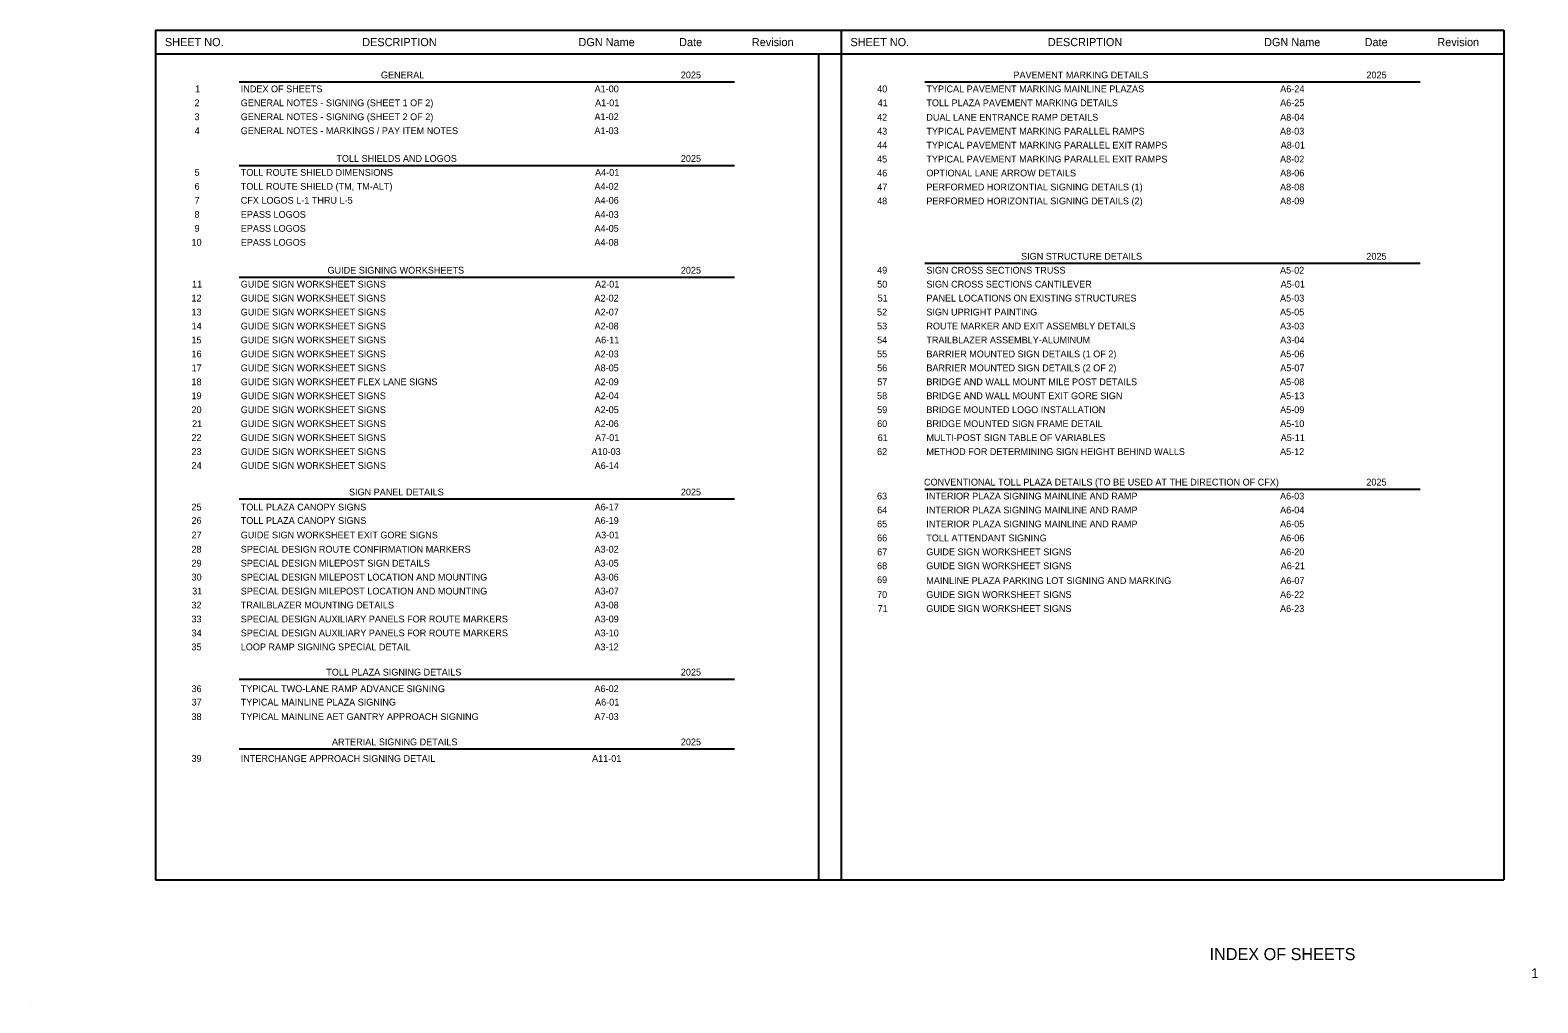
# Model space of a CAD drawing. Extents: x 2479979.8 to 2479999.3, y 3680687.9 to 3680700.4.
import ezdxf

# ---------------------------------------------------------------- set-up
doc = ezdxf.new("R2010")
doc.units = 0
for name, color, linetype in [('AdhocPoint_dp', 7, 'Continuous'), ('SumBoxLines_dp', 7, 'Continuous'), ('TextLabel', 7, 'Continuous'), ('TextMisc', 7, 'Continuous'), ('TextShtNo', 7, 'Continuous')]:
    doc.layers.add(name, color=color, linetype=linetype)

msp = doc.modelspace()

# ---------------------------------------------------------------- linework, layer by layer
at = {"layer": 'AdhocPoint_dp'}
msp.add_line((2479979.842, 3680687.871), (2479979.842, 3680687.871), dxfattribs=at)
at = {"layer": 'SumBoxLines_dp'}
for p, q in [((2479981.458, 3680700.422), (2479998.85, 3680700.422)), ((2479981.458, 3680700.422), (2479981.458, 3680689.458)), ((2479990.3, 3680700.422), (2479990.3, 3680690.034)), ((2479998.85, 3680700.422), (2479998.85, 3680689.458)), ((2479981.458, 3680700.114), (2479998.85, 3680700.114)), ((2479981.458, 3680700.114), (2479998.85, 3680700.114)), ((2479990.008, 3680700.114), (2479990.008, 3680691.294)), ((2479990.008, 3680700.025), (2479990.008, 3680689.458)), ((2479990.3, 3680700.025), (2479990.3, 3680689.458)), ((2479982.538, 3680699.754), (2479988.928, 3680699.754)), ((2479982.538, 3680699.754), (2479988.928, 3680699.754)), ((2479991.381, 3680699.754), (2479997.771, 3680699.754)), ((2479991.381, 3680699.754), (2479997.771, 3680699.754)), ((2479982.538, 3680698.675), (2479988.928, 3680698.675)), ((2479982.538, 3680698.675), (2479988.928, 3680698.675)), ((2479991.381, 3680697.414), (2479997.771, 3680697.414)), ((2479991.381, 3680697.414), (2479997.771, 3680697.414)), ((2479982.538, 3680697.234), (2479988.928, 3680697.234)), ((2479982.538, 3680697.234), (2479988.928, 3680697.234)), ((2479991.38, 3680694.5), (2479997.77, 3680694.5)), ((2479991.38, 3680694.5), (2479997.77, 3680694.5)), ((2479982.538, 3680694.372), (2479988.928, 3680694.372)), ((2479982.538, 3680692.047), (2479988.928, 3680692.047)), ((2479982.538, 3680692.047), (2479988.928, 3680692.047)), ((2479982.538, 3680691.147), (2479988.928, 3680691.147)), ((2479982.538, 3680691.147), (2479988.928, 3680691.147)), ((2479981.458, 3680689.458), (2479998.85, 3680689.458))]:
    msp.add_line(p, q, dxfattribs=at)

# ---------------------------------------------------------------- texts
at = {"layer": 'TextLabel'}
for s, height, p in [('SHEET NO.', 0.105, (2479981.58, 3680700.215)), ('DESCRIPTION', 0.105, (2479984.125, 3680700.215)), ('DGN Name', 0.105, (2479986.914, 3680700.215)), ('Date', 0.105, (2479988.212, 3680700.215)), ('Revision', 0.105, (2479989.15, 3680700.215)), ('SHEET NO.', 0.105, (2479990.422, 3680700.215)), ('DESCRIPTION', 0.105, (2479992.968, 3680700.215)), ('DGN Name', 0.105, (2479995.757, 3680700.215)), ('Date', 0.105, (2479997.054, 3680700.215)), ('Revision', 0.105, (2479997.992, 3680700.215)), ('GENERAL', 0.0875, (2479984.366, 3680699.8)), ('2025', 0.0875, (2479988.234, 3680699.8)), ('PAVEMENT MARKING DETAILS', 0.0875, (2479992.524, 3680699.8)), ('2025', 0.0875, (2479997.077, 3680699.8)), ('2', 0.0875, (2479981.961, 3680699.44)), ('1', 0.0875, (2479981.969, 3680699.62)), ('GENERAL NOTES - SIGNING (SHEET 1 OF 2)', 0.0875, (2479982.558, 3680699.44)), ('INDEX OF SHEETS', 0.0875, (2479982.558, 3680699.62)), ('A1-00', 0.0875, (2479987.121, 3680699.62)), ('A1-01', 0.0875, (2479987.128, 3680699.44)), ('40', 0.0875, (2479990.766, 3680699.62)), ('41', 0.0875, (2479990.773, 3680699.44)), ('TYPICAL PAVEMENT MARKING MAINLINE PLAZAS', 0.0875, (2479991.401, 3680699.62)), ('TOLL PLAZA PAVEMENT MARKING DETAILS', 0.0875, (2479991.401, 3680699.44)), ('A6-25', 0.0875, (2479995.964, 3680699.44)), ('A6-24', 0.0875, (2479995.965, 3680699.62)), ('3', 0.0875, (2479981.961, 3680699.26)), ('GENERAL NOTES - SIGNING (SHEET 2 OF 2)', 0.0875, (2479982.558, 3680699.26)), ('A1-02', 0.0875, (2479987.12, 3680699.26)), ('42', 0.0875, (2479990.765, 3680699.254)), ('DUAL LANE ENTRANCE RAMP DETAILS', 0.0875, (2479991.401, 3680699.254)), ('A8-04', 0.0875, (2479995.965, 3680699.254)), ('4', 0.0875, (2479981.963, 3680699.08)), ('GENERAL NOTES - MARKINGS / PAY ITEM NOTES', 0.0875, (2479982.558, 3680699.08)), ('A1-03', 0.0875, (2479987.12, 3680699.08)), ('43', 0.0875, (2479990.765, 3680699.074)), ('TYPICAL PAVEMENT MARKING PARALLEL RAMPS', 0.0875, (2479991.401, 3680699.074)), ('A8-03', 0.0875, (2479995.963, 3680699.074)), ('44', 0.0875, (2479990.766, 3680698.894)), ('TYPICAL PAVEMENT MARKING PARALLEL EXIT RAMPS', 0.0875, (2479991.401, 3680698.894)), ('A8-01', 0.0875, (2479995.971, 3680698.894)), ('TOLL SHIELDS AND LOGOS', 0.0875, (2479983.791, 3680698.722)), ('2025', 0.0875, (2479988.234, 3680698.722)), ('45', 0.0875, (2479990.765, 3680698.714)), ('TYPICAL PAVEMENT MARKING PARALLEL EXIT RAMPS', 0.0875, (2479991.401, 3680698.714)), ('A8-02', 0.0875, (2479995.963, 3680698.714)), ('5', 0.0875, (2479981.962, 3680698.542)), ('TOLL ROUTE SHIELD DIMENSIONS', 0.0875, (2479982.558, 3680698.542)), ('A4-01', 0.0875, (2479987.128, 3680698.542)), ('46', 0.0875, (2479990.766, 3680698.534)), ('OPTIONAL LANE ARROW DETAILS', 0.0875, (2479991.401, 3680698.534)), ('A8-06', 0.0875, (2479995.964, 3680698.534)), ('6', 0.0875, (2479981.962, 3680698.362)), ('TOLL ROUTE SHIELD (TM, TM-ALT)', 0.0875, (2479982.558, 3680698.362)), ('A4-02', 0.0875, (2479987.12, 3680698.362)), ('47', 0.0875, (2479990.767, 3680698.354)), ('PERFORMED HORIZONTIAL SIGNING DETAILS (1)', 0.0875, (2479991.401, 3680698.354)), ('A8-08', 0.0875, (2479995.963, 3680698.354)), ('7', 0.0875, (2479981.963, 3680698.182)), ('CFX LOGOS L-1 THRU L-5', 0.0875, (2479982.558, 3680698.182)), ('A4-06', 0.0875, (2479987.121, 3680698.182)), ('48', 0.0875, (2479990.765, 3680698.174)), ('PERFORMED HORIZONTIAL SIGNING DETAILS (2)', 0.0875, (2479991.401, 3680698.174)), ('A8-09', 0.0875, (2479995.964, 3680698.174)), ('8', 0.0875, (2479981.961, 3680698)), ('EPASS LOGOS', 0.0875, (2479982.558, 3680698)), ('A4-03', 0.0875, (2479987.12, 3680698)), ('9', 0.0875, (2479981.962, 3680697.82)), ('EPASS LOGOS', 0.0875, (2479982.558, 3680697.82)), ('A4-05', 0.0875, (2479987.121, 3680697.82)), ('10', 0.0875, (2479981.923, 3680697.64)), ('EPASS LOGOS', 0.0875, (2479982.558, 3680697.64)), ('A4-08', 0.0875, (2479987.12, 3680697.64)), ('SIGN STRUCTURE DETAILS', 0.0875, (2479992.623, 3680697.46)), ('2025', 0.0875, (2479997.076, 3680697.46)), ('11', 0.0875, (2479981.93, 3680697.1)), ('GUIDE SIGN WORKSHEET SIGNS', 0.0875, (2479982.558, 3680697.1)), ('GUIDE SIGNING WORKSHEETS', 0.0875, (2479983.677, 3680697.28)), ('A2-01', 0.0875, (2479987.128, 3680697.1)), ('2025', 0.0875, (2479988.234, 3680697.28)), ('49', 0.0875, (2479990.766, 3680697.28)), ('50', 0.0875, (2479990.766, 3680697.1)), ('SIGN CROSS SECTIONS TRUSS', 0.0875, (2479991.401, 3680697.28)), ('SIGN CROSS SECTIONS CANTILEVER', 0.0875, (2479991.401, 3680697.1)), ('A5-02', 0.0875, (2479995.963, 3680697.28)), ('A5-01', 0.0875, (2479995.971, 3680697.1)), ('12', 0.0875, (2479981.922, 3680696.92)), ('GUIDE SIGN WORKSHEET SIGNS', 0.0875, (2479982.558, 3680696.92)), ('A2-02', 0.0875, (2479987.12, 3680696.92)), ('51', 0.0875, (2479990.773, 3680696.92)), ('PANEL LOCATIONS ON EXISTING STRUCTURES', 0.0875, (2479991.401, 3680696.92)), ('A5-03', 0.0875, (2479995.963, 3680696.92)), ('13', 0.0875, (2479981.922, 3680696.74)), ('GUIDE SIGN WORKSHEET SIGNS', 0.0875, (2479982.558, 3680696.74)), ('A2-07', 0.0875, (2479987.122, 3680696.74)), ('52', 0.0875, (2479990.765, 3680696.74)), ('SIGN UPRIGHT PAINTING', 0.0875, (2479991.401, 3680696.74)), ('A5-05', 0.0875, (2479995.963, 3680696.74)), ('14', 0.0875, (2479981.924, 3680696.56)), ('GUIDE SIGN WORKSHEET SIGNS', 0.0875, (2479982.558, 3680696.56)), ('A2-08', 0.0875, (2479987.12, 3680696.56)), ('53', 0.0875, (2479990.765, 3680696.56)), ('ROUTE MARKER AND EXIT ASSEMBLY DETAILS', 0.0875, (2479991.401, 3680696.56)), ('A3-03', 0.0875, (2479995.963, 3680696.56)), ('15', 0.0875, (2479981.922, 3680696.38)), ('GUIDE SIGN WORKSHEET SIGNS', 0.0875, (2479982.558, 3680696.38)), ('A6-11', 0.0875, (2479987.128, 3680696.38)), ('54', 0.0875, (2479990.766, 3680696.38)), ('TRAILBLAZER ASSEMBLY-ALUMINUM', 0.0875, (2479991.401, 3680696.38)), ('A3-04', 0.0875, (2479995.965, 3680696.38)), ('16', 0.0875, (2479981.923, 3680696.2)), ('GUIDE SIGN WORKSHEET SIGNS', 0.0875, (2479982.558, 3680696.2)), ('A2-03', 0.0875, (2479987.12, 3680696.2)), ('55', 0.0875, (2479990.765, 3680696.2)), ('BARRIER MOUNTED SIGN DETAILS (1 OF 2)', 0.0875, (2479991.401, 3680696.2)), ('A5-06', 0.0875, (2479995.964, 3680696.2)), ('17', 0.0875, (2479981.924, 3680696.02)), ('GUIDE SIGN WORKSHEET SIGNS', 0.0875, (2479982.558, 3680696.02)), ('A8-05', 0.0875, (2479987.121, 3680696.02)), ('56', 0.0875, (2479990.766, 3680696.02)), ('BARRIER MOUNTED SIGN DETAILS (2 OF 2)', 0.0875, (2479991.401, 3680696.02)), ('A5-07', 0.0875, (2479995.965, 3680696.02)), ('18', 0.0875, (2479981.922, 3680695.84)), ('GUIDE SIGN WORKSHEET FLEX LANE SIGNS', 0.0875, (2479982.558, 3680695.84)), ('A2-09', 0.0875, (2479987.121, 3680695.84)), ('57', 0.0875, (2479990.767, 3680695.84)), ('BRIDGE AND WALL MOUNT MILE POST DETAILS', 0.0875, (2479991.401, 3680695.84)), ('A5-08', 0.0875, (2479995.963, 3680695.84)), ('19', 0.0875, (2479981.923, 3680695.66)), ('GUIDE SIGN WORKSHEET SIGNS', 0.0875, (2479982.558, 3680695.66)), ('A2-04', 0.0875, (2479987.122, 3680695.66)), ('58', 0.0875, (2479990.765, 3680695.66)), ('BRIDGE AND WALL MOUNT EXIT GORE SIGN', 0.0875, (2479991.401, 3680695.66)), ('A5-13', 0.0875, (2479995.963, 3680695.66)), ('20', 0.0875, (2479981.923, 3680695.48)), ('GUIDE SIGN WORKSHEET SIGNS', 0.0875, (2479982.558, 3680695.48)), ('A2-05', 0.0875, (2479987.121, 3680695.48)), ('59', 0.0875, (2479990.766, 3680695.48)), ('BRIDGE MOUNTED LOGO INSTALLATION', 0.0875, (2479991.401, 3680695.48)), ('A5-09', 0.0875, (2479995.964, 3680695.48)), ('21', 0.0875, (2479981.93, 3680695.3)), ('GUIDE SIGN WORKSHEET SIGNS', 0.0875, (2479982.558, 3680695.3)), ('A2-06', 0.0875, (2479987.121, 3680695.3)), ('60', 0.0875, (2479990.766, 3680695.3)), ('BRIDGE MOUNTED SIGN FRAME DETAIL', 0.0875, (2479991.401, 3680695.3)), ('A5-10', 0.0875, (2479995.964, 3680695.3)), ('22', 0.0875, (2479981.922, 3680695.12)), ('GUIDE SIGN WORKSHEET SIGNS', 0.0875, (2479982.558, 3680695.12)), ('A7-01', 0.0875, (2479987.128, 3680695.12)), ('61', 0.0875, (2479990.773, 3680695.12)), ('MULTI-POST SIGN TABLE OF VARIABLES', 0.0875, (2479991.401, 3680695.12)), ('A5-11', 0.0875, (2479995.971, 3680695.12)), ('23', 0.0875, (2479981.922, 3680694.94)), ('GUIDE SIGN WORKSHEET SIGNS', 0.0875, (2479982.558, 3680694.94)), ('A10-03', 0.0875, (2479987.081, 3680694.94)), ('62', 0.0875, (2479990.765, 3680694.94)), ('METHOD FOR DETERMINING SIGN HEIGHT BEHIND WALLS', 0.0875, (2479991.401, 3680694.94)), ('A5-12', 0.0875, (2479995.963, 3680694.94)), ('24', 0.0875, (2479981.924, 3680694.76)), ('GUIDE SIGN WORKSHEET SIGNS', 0.0875, (2479982.558, 3680694.76)), ('A6-14', 0.0875, (2479987.122, 3680694.76)), ('SIGN PANEL DETAILS', 0.0875, (2479983.954, 3680694.418)), ('2025', 0.0875, (2479988.234, 3680694.418)), ('CONVENTIONAL TOLL PLAZA DETAILS (TO BE USED AT THE DIRECTION OF CFX)', 0.0875, (2479991.371, 3680694.546)), ('2025', 0.0875, (2479997.076, 3680694.546)), ('25', 0.0875, (2479981.922, 3680694.224)), ('TOLL PLAZA CANOPY SIGNS', 0.0875, (2479982.558, 3680694.224)), ('A6-17', 0.0875, (2479987.122, 3680694.224)), ('63', 0.0875, (2479990.764, 3680694.366)), ('64', 0.0875, (2479990.766, 3680694.186)), ('INTERIOR PLAZA SIGNING MAINLINE AND RAMP', 0.0875, (2479991.4, 3680694.366)), ('INTERIOR PLAZA SIGNING MAINLINE AND RAMP', 0.0875, (2479991.4, 3680694.186)), ('A6-03', 0.0875, (2479995.963, 3680694.366)), ('A6-04', 0.0875, (2479995.964, 3680694.186)), ('26', 0.0875, (2479981.923, 3680694.051)), ('TOLL PLAZA CANOPY SIGNS', 0.0875, (2479982.558, 3680694.051)), ('A6-19', 0.0875, (2479987.121, 3680694.051)), ('65', 0.0875, (2479990.765, 3680694.006)), ('INTERIOR PLAZA SIGNING MAINLINE AND RAMP', 0.0875, (2479991.4, 3680694.006)), ('A6-05', 0.0875, (2479995.963, 3680694.006)), ('27', 0.0875, (2479981.924, 3680693.864)), ('GUIDE SIGN WORKSHEET EXIT GORE SIGNS', 0.0875, (2479982.558, 3680693.864)), ('A3-01', 0.0875, (2479987.128, 3680693.864)), ('66', 0.0875, (2479990.765, 3680693.826)), ('TOLL ATTENDANT SIGNING', 0.0875, (2479991.4, 3680693.826)), ('A6-06', 0.0875, (2479995.964, 3680693.826)), ('28', 0.0875, (2479981.922, 3680693.68)), ('SPECIAL DESIGN ROUTE CONFIRMATION MARKERS', 0.0875, (2479982.558, 3680693.68)), ('A3-02', 0.0875, (2479987.12, 3680693.68)), ('67', 0.0875, (2479990.766, 3680693.646)), ('GUIDE SIGN WORKSHEET SIGNS ', 0.0875, (2479991.4, 3680693.646)), ('A6-20', 0.0875, (2479995.964, 3680693.646)), ('29', 0.0875, (2479981.923, 3680693.5)), ('SPECIAL DESIGN MILEPOST SIGN DETAILS', 0.0875, (2479982.558, 3680693.5)), ('A3-05', 0.0875, (2479987.121, 3680693.5)), ('68', 0.0875, (2479990.765, 3680693.466)), ('GUIDE SIGN WORKSHEET SIGNS ', 0.0875, (2479991.4, 3680693.466)), ('A6-21', 0.0875, (2479995.971, 3680693.466)), ('30', 0.0875, (2479981.923, 3680693.32)), ('SPECIAL DESIGN MILEPOST LOCATION AND MOUNTING', 0.0875, (2479982.558, 3680693.32)), ('A3-06', 0.0875, (2479987.121, 3680693.32)), ('69', 0.0875, (2479990.765, 3680693.286)), ('MAINLINE PLAZA PARKING LOT SIGNING AND MARKING', 0.0875, (2479991.4, 3680693.275)), ('A6-07', 0.0875, (2479995.965, 3680693.275)), ('31', 0.0875, (2479981.93, 3680693.14)), ('SPECIAL DESIGN MILEPOST LOCATION AND MOUNTING', 0.0875, (2479982.558, 3680693.14)), ('A3-07', 0.0875, (2479987.122, 3680693.14)), ('70', 0.0875, (2479990.765, 3680693.095)), ('GUIDE SIGN WORKSHEET SIGNS', 0.0875, (2479991.4, 3680693.095)), ('A6-22', 0.0875, (2479995.963, 3680693.095)), ('32', 0.0875, (2479981.922, 3680692.96)), ('TRAILBLAZER MOUNTING DETAILS', 0.0875, (2479982.558, 3680692.96)), ('A3-08', 0.0875, (2479987.12, 3680692.96)), ('71', 0.0875, (2479990.772, 3680692.915)), ('GUIDE SIGN WORKSHEET SIGNS', 0.0875, (2479991.4, 3680692.915)), ('A6-23', 0.0875, (2479995.963, 3680692.915)), ('33', 0.0875, (2479981.922, 3680692.78)), ('SPECIAL DESIGN AUXILIARY PANELS FOR ROUTE MARKERS', 0.0875, (2479982.558, 3680692.78)), ('A3-09', 0.0875, (2479987.121, 3680692.78)), ('34', 0.0875, (2479981.924, 3680692.6)), ('SPECIAL DESIGN AUXILIARY PANELS FOR ROUTE MARKERS', 0.0875, (2479982.558, 3680692.6)), ('A3-10', 0.0875, (2479987.121, 3680692.6)), ('35', 0.0875, (2479981.922, 3680692.42)), ('LOOP RAMP SIGNING SPECIAL DETAIL', 0.0875, (2479982.558, 3680692.42)), ('A3-12', 0.0875, (2479987.12, 3680692.42)), ('TOLL PLAZA SIGNING DETAILS', 0.0875, (2479983.661, 3680692.094)), ('2025', 0.0875, (2479988.234, 3680692.094)), ('36', 0.0875, (2479981.923, 3680691.88)), ('TYPICAL TWO-LANE RAMP ADVANCE SIGNING', 0.0875, (2479982.558, 3680691.88)), ('A6-02', 0.0875, (2479987.12, 3680691.88)), ('37', 0.0875, (2479981.924, 3680691.707)), ('TYPICAL MAINLINE PLAZA SIGNING', 0.0875, (2479982.558, 3680691.707)), ('A6-01', 0.0875, (2479987.128, 3680691.707)), ('38', 0.0875, (2479981.922, 3680691.52)), ('TYPICAL MAINLINE AET GANTRY APPROACH SIGNING', 0.0875, (2479982.558, 3680691.52)), ('A7-03', 0.0875, (2479987.12, 3680691.52)), ('ARTERIAL SIGNING DETAILS', 0.0875, (2479983.734, 3680691.194)), ('2025', 0.0875, (2479988.234, 3680691.194)), ('39', 0.0875, (2479981.923, 3680690.98)), ('INTERCHANGE APPROACH SIGNING DETAIL', 0.0875, (2479982.558, 3680690.98)), ('A11-01', 0.0875, (2479987.089, 3680690.98))]:
    msp.add_text(s, height=height, dxfattribs=at).set_placement(p)
at = {"layer": 'TextMisc'}
msp.add_text('       INDEX OF SHEETS         ', height=0.15625, rotation=360, dxfattribs=at).set_placement((2479994.648, 3680688.422))
at = {"layer": 'TextShtNo'}
msp.add_text('  1  ', height=0.125, rotation=360, dxfattribs=at).set_placement((2479999.11, 3680688.19))

doc.saveas('drawing.dxf')
